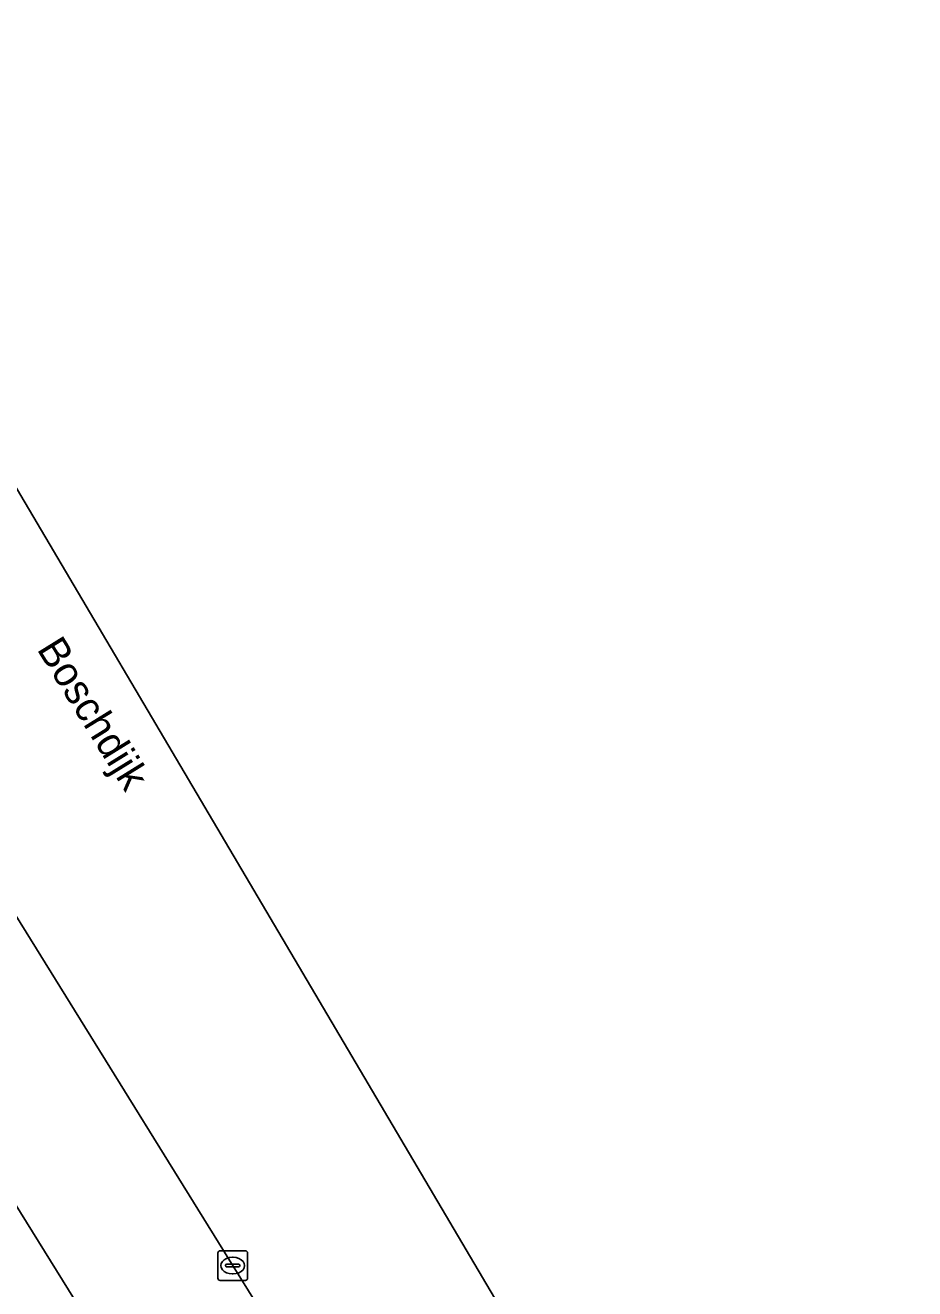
# Model space of a CAD drawing. Extents: x 160304 to 160955, y 383684 to 384161.
# Drawn here: x 160779.74 to 160809.81, y 384074.11 to 384116.83 of the extents above; entities that cross this region are included whole.
import ezdxf

# ---------------------------------------------------------------- set-up
doc = ezdxf.new("R2010")
doc.units = 0
for name, color, linetype in [('IMGEO_Fietspad_open', 7, 'Continuous'), ('IMGEO_Groenvoorziening', 7, 'Continuous'), ('IMGEO_Haag', 7, 'Continuous'), ('IMGEO_Kolk', 7, 'Continuous'), ('IMGEO_Openbare_ruimte_label', 7, 'Continuous'), ('IMGEO_Rijbaan_lokaal_gesloten', 7, 'Continuous')]:
    doc.layers.add(name, color=color, linetype=linetype)

msp = doc.modelspace()

# ---------------------------------------------------------------- linework, layer by layer
at = {"layer": 'IMGEO_Fietspad_open'}
msp.add_lwpolyline([(160842.328, 383975.591), (160832.842, 383990.888), (160827.177, 384000), (160814.975, 384019.629), (160813.456, 384022.072), (160805.259, 384035.309), (160768.526, 384094.486), (160764.835, 384100.432), (160758.942, 384109.926), (160757.079, 384112.871)], dxfattribs=at)
at = {"layer": 'IMGEO_Groenvoorziening'}
for points in [[(160786.766, 384074.88), (160774.746, 384094.262), (160772.522, 384097.674), (160768.7, 384103.329)], [(160768.526, 384094.486), (160805.259, 384035.309), (160806.841, 384036.335), (160804.538, 384041.052), (160799.23, 384052.134), (160793.098, 384064.312)], [(160790.082, 384069.549), (160786.766, 384074.88)]]:
    msp.add_lwpolyline(points, dxfattribs=at)
at = {"layer": 'IMGEO_Haag'}
for points in [[(160790.082, 384069.549), (160786.766, 384074.88), (160774.746, 384094.262), (160772.522, 384097.674), (160768.7, 384103.329)], [(160768.526, 384094.486), (160805.259, 384035.309), (160806.841, 384036.335), (160804.538, 384041.052), (160799.23, 384052.134), (160793.098, 384064.312)]]:
    msp.add_lwpolyline(points, dxfattribs=at)
at = {"layer": 'IMGEO_Kolk'}
for p, q in [((160786.254, 384074.47), (160786.254, 384075.322)), ((160786.329, 384075.396), (160787.181, 384075.396)), ((160787.255, 384075.322), (160787.255, 384074.47)), ((160786.513, 384074.89), (160786.513, 384074.902)), ((160786.556, 384074.939), (160786.954, 384074.939)), ((160786.742, 384075.176), (160786.767, 384075.176)), ((160786.997, 384074.902), (160786.997, 384074.89)), ((160786.951, 384074.853), (160786.553, 384074.853)), ((160786.765, 384074.616), (160786.74, 384074.616)), ((160787.181, 384074.396), (160786.329, 384074.396))]:
    msp.add_line(p, q, dxfattribs=at)
for points in [[(160786.254, 384074.47), (160786.254, 384075.322)], [(160786.329, 384075.396), (160787.181, 384075.396)], [(160787.255, 384075.322), (160787.255, 384074.47)], [(160787.181, 384074.396), (160786.329, 384074.396)]]:
    msp.add_lwpolyline(points, dxfattribs=at)
for centre, radius, start, end in [((160786.331, 384075.32), 0.0765, 91.552, 178.448), ((160786.331, 384075.32), 0.0765, 91.552, 178.448), ((160787.179, 384075.32), 0.0765, 1.552, 88.448), ((160787.179, 384075.32), 0.0765, 1.552, 88.448), ((160786.553, 384074.899), 0.0403, 85.8775, 175.7526), ((160786.55, 384074.889), 0.0366, 178.938, 274.7102), ((160786.954, 384074.896), 0.043, 264.8664, 352.4533), ((160786.958, 384074.901), 0.0386, 1.7309, 96.639), ((160786.331, 384074.472), 0.0765, 181.552, 268.448), ((160786.331, 384074.472), 0.0765, 181.552, 268.448), ((160787.179, 384074.472), 0.0765, 271.552, 358.448), ((160787.179, 384074.472), 0.0765, 271.552, 358.448)]:
    msp.add_arc(centre, radius, start, end, dxfattribs=at)
for centre, major_axis, ratio, start_param, end_param in [((160786.741, 384074.896), (-0.387, 0.002), 0.722429, 4.712389, 7.853982), ((160786.766, 384074.896), (-0.39, 0.002), 0.717154, 1.570796, 4.712389)]:
    msp.add_ellipse(centre, major_axis=major_axis, ratio=ratio, start_param=start_param, end_param=end_param, dxfattribs=at)
at = {"layer": 'IMGEO_Rijbaan_lokaal_gesloten'}
for points in [[(160829.462, 384016.251), (160833.83, 384010.732), (160840.534, 384002.625), (160841.388, 384001.592), (160842.704, 384000), (160849.266, 383992.065), (160868.119, 383969.355), (160879.192, 383956), (160880.365, 383956.615), (160878.693, 383959.094), (160821.298, 384030.284), (160770.19, 384116.828)], [(160777.428, 384098.352), (160775.75, 384100.796), (160766.365, 384114.473), (160762.643, 384112.202), (160764.513, 384109.525), (160765.165, 384108.56), (160768.7, 384103.329), (160772.522, 384097.674), (160774.746, 384094.262), (160786.766, 384074.88), (160790.082, 384069.549)]]:
    msp.add_lwpolyline(points, dxfattribs=at)

# ---------------------------------------------------------------- texts
at = {"layer": 'IMGEO_Openbare_ruimte_label'}
msp.add_text('Boschdijk', height=1, rotation=301.7989, dxfattribs=at).set_placement((160780.114, 384095.738))

doc.saveas('drawing.dxf')
